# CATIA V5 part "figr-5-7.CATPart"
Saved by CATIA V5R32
Part number: Part1
Bounding box of the stored display mesh (mm): x 0 to 150, y -70 to 70, z -150 to 69.804
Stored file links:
  D:\PROJECTS\Project 2022\CATIA V5 6R 2022\Resources\Part Files\c05_catia_v5_6r2022_prt\figr-5-7.CATPart
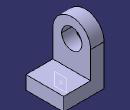
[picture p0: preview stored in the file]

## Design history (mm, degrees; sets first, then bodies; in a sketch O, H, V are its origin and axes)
Set1
  Plane1: type OffsetPt, RefPlane face of Pad2, RefPoint Sketch3
Body1 (main body)
  Sketch1 on yz-plane, origin (0, 0, 0), H (0, 1, 0), V (0, 0, 1)
    arc A1 centre (0, 0) radius 70 from (70, 0) to (-70, 0) ccw
    point P1 (70, 0)
    point P2 (-70, 0)
    line L1 (-70, 0) -> (-70, -150)
    line L2 (-70, -150) -> (70, -150)
    line L3 (70, -150) -> (70, 0)
    circle A2 centre (0, 0) radius 37.5
    radius A1 = 70
    radius A2 = 37.5
    distance O L2 = 150
    coincidence: P1 H, P2 H
    tangency: L1 A1, L3 A1
    horizontal: L2 H
  Pad1: profile Sketch1, direction (1, 0, 0), length 50
  Sketch2 on face of Pad1, origin (50, 0, 0), H (0, 1, 0), V (0, 0, 1)
    line L1 (-70, -150) -> (70, -150)
    line L2 (70, -150) -> (70, -100)
    line L3 (70, -100) -> (-70, -100)
    line L4 (-70, -100) -> (-70, -150)
    reference projected line E1 (-70, -150) -> (70, -150) from edge [face of Pad1 | face of Pad1]
    reference projected line E2 (-70, 0) -> (-70, -150) from edge [face of Pad1 | face of Pad1]
    reference projected line E3 (70, -150) -> (70, 0) from edge [face of Pad1 | face of Pad1]
    length L2 = 50
    horizontal: L1 H, L3 H
    vertical: L2 V, L4 V
    coincidence: L1 E1, E2 L4, L2 E3
  Pad2: profile Sketch2, direction (1, 0, 0), length 100
  Sketch3 on face of Pad2, origin (0, 0, -100), H (1, 0, 0), V (0, 1, 0)
    point P1 (110, 20)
